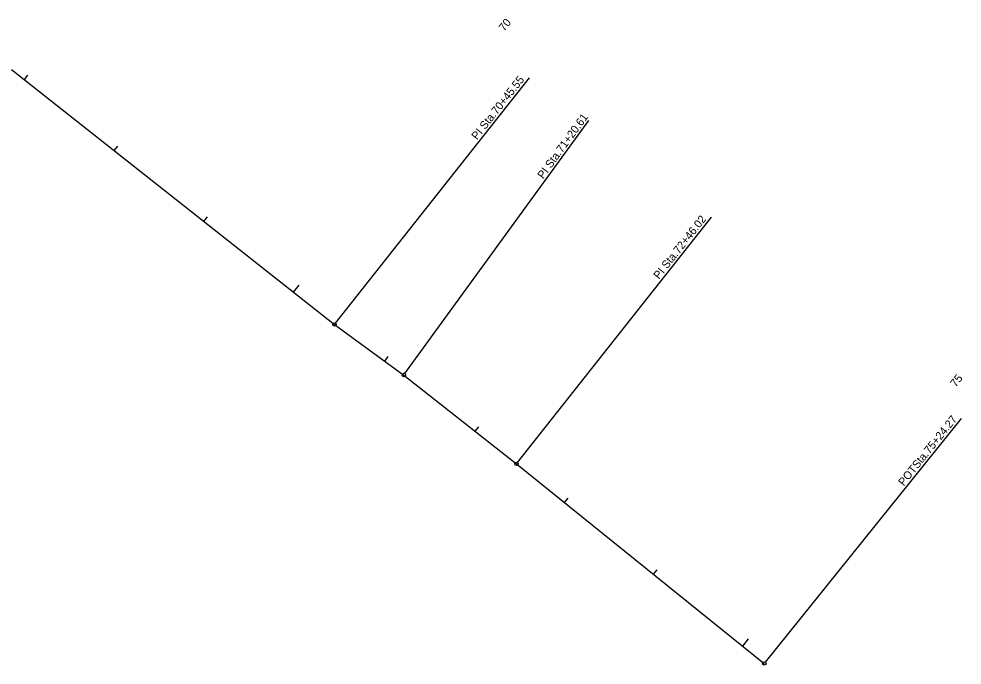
# Model space of a CAD drawing. Extents: x 554184 to 558768, y 503077 to 507235.
# Drawn here: x 557943 to 558768, y 506377 to 506942 of the extents above; entities that cross this region are included whole.
import ezdxf

# ---------------------------------------------------------------- set-up
doc = ezdxf.new("R2010")
doc.units = 0
for name, color, linetype in [('Prop Horizontal Alignment Station Label', 7, 'Continuous'), ('Prop Horizontal Alignment Tick Label', 7, 'Continuous'), ('Prop Horizontal Alignment Tick Large', 7, 'Continuous'), ('Prop Horizontal Alignment Tick Small', 7, 'Continuous'), ('Prop Vertical Profile Grade', 7, 'Continuous')]:
    doc.layers.add(name, color=color, linetype=linetype)

msp = doc.modelspace()

# ---------------------------------------------------------------- linework, layer by layer
at = {"layer": 'Prop Horizontal Alignment Station Label'}
for p, q in [((558220.03, 506676.32), (558389.55, 506890.95)), ((558280.7, 506632.22), (558441.5, 506853.46)), ((558379.17, 506554.45), (558548.69, 506769.08)), ((558595.94, 506379.98), (558767.42, 506593.04))]:
    msp.add_line(p, q, dxfattribs=at)
for centre in [(558219.1, 506675.14), (558279.82, 506631.01), (558378.24, 506553.28), (558595, 506378.81)]:
    msp.add_circle(centre, 1.5, dxfattribs=at)
at = {"layer": 'Prop Horizontal Alignment Tick Large'}
for p, q in [((558183.36, 506703.37), (558188.32, 506709.65)), ((558576.09, 506394.03), (558581.11, 506400.26))]:
    msp.add_line(p, q, dxfattribs=at)
at = {"layer": 'Prop Horizontal Alignment Tick Small'}
for p, q in [((557947.93, 506889.31), (557951.03, 506893.24)), ((558026.41, 506827.33), (558029.51, 506831.26)), ((558104.88, 506765.35), (558107.98, 506769.27)), ((558263.15, 506643.12), (558266.09, 506647.17)), ((558342.12, 506581.8), (558345.22, 506585.72)), ((558420.29, 506519.43), (558423.42, 506523.33)), ((558498.19, 506456.73), (558501.33, 506460.63))]:
    msp.add_line(p, q, dxfattribs=at)
at = {"layer": 'Prop Vertical Profile Grade'}
for p, q in [((557936.7, 506898.19), (558219.1, 506675.14)), ((558219.1, 506675.14), (558279.82, 506631.01)), ((558279.82, 506631.01), (558378.24, 506553.28)), ((558378.24, 506553.28), (558595, 506378.81))]:
    msp.add_line(p, q, dxfattribs=at)

# ---------------------------------------------------------------- texts
at = {"layer": 'Prop Horizontal Alignment Station Label'}
for s, rotation, p in [('PI Sta.70+45.55', 51.69784, (558343.74, 506836.18)), ('PI Sta.71+20.61', 53.98845, (558401.65, 506802.03)), ('PI Sta.72+46.02', 51.69784, (558502.88, 506714.32)), ('POTSta.75+24.27', 51.17061, (558716.94, 506533.51))]:
    msp.add_text(s, height=7, rotation=rotation, dxfattribs=at).set_placement(p)
at = {"layer": 'Prop Horizontal Alignment Tick Label'}
for s, rotation, p in [('70', 51.69784, (558367.63, 506931.03)), ('75', 51.17061, (558762.4, 506619.92))]:
    msp.add_text(s, height=7, rotation=rotation, dxfattribs=at).set_placement(p)

doc.saveas('drawing.dxf')
